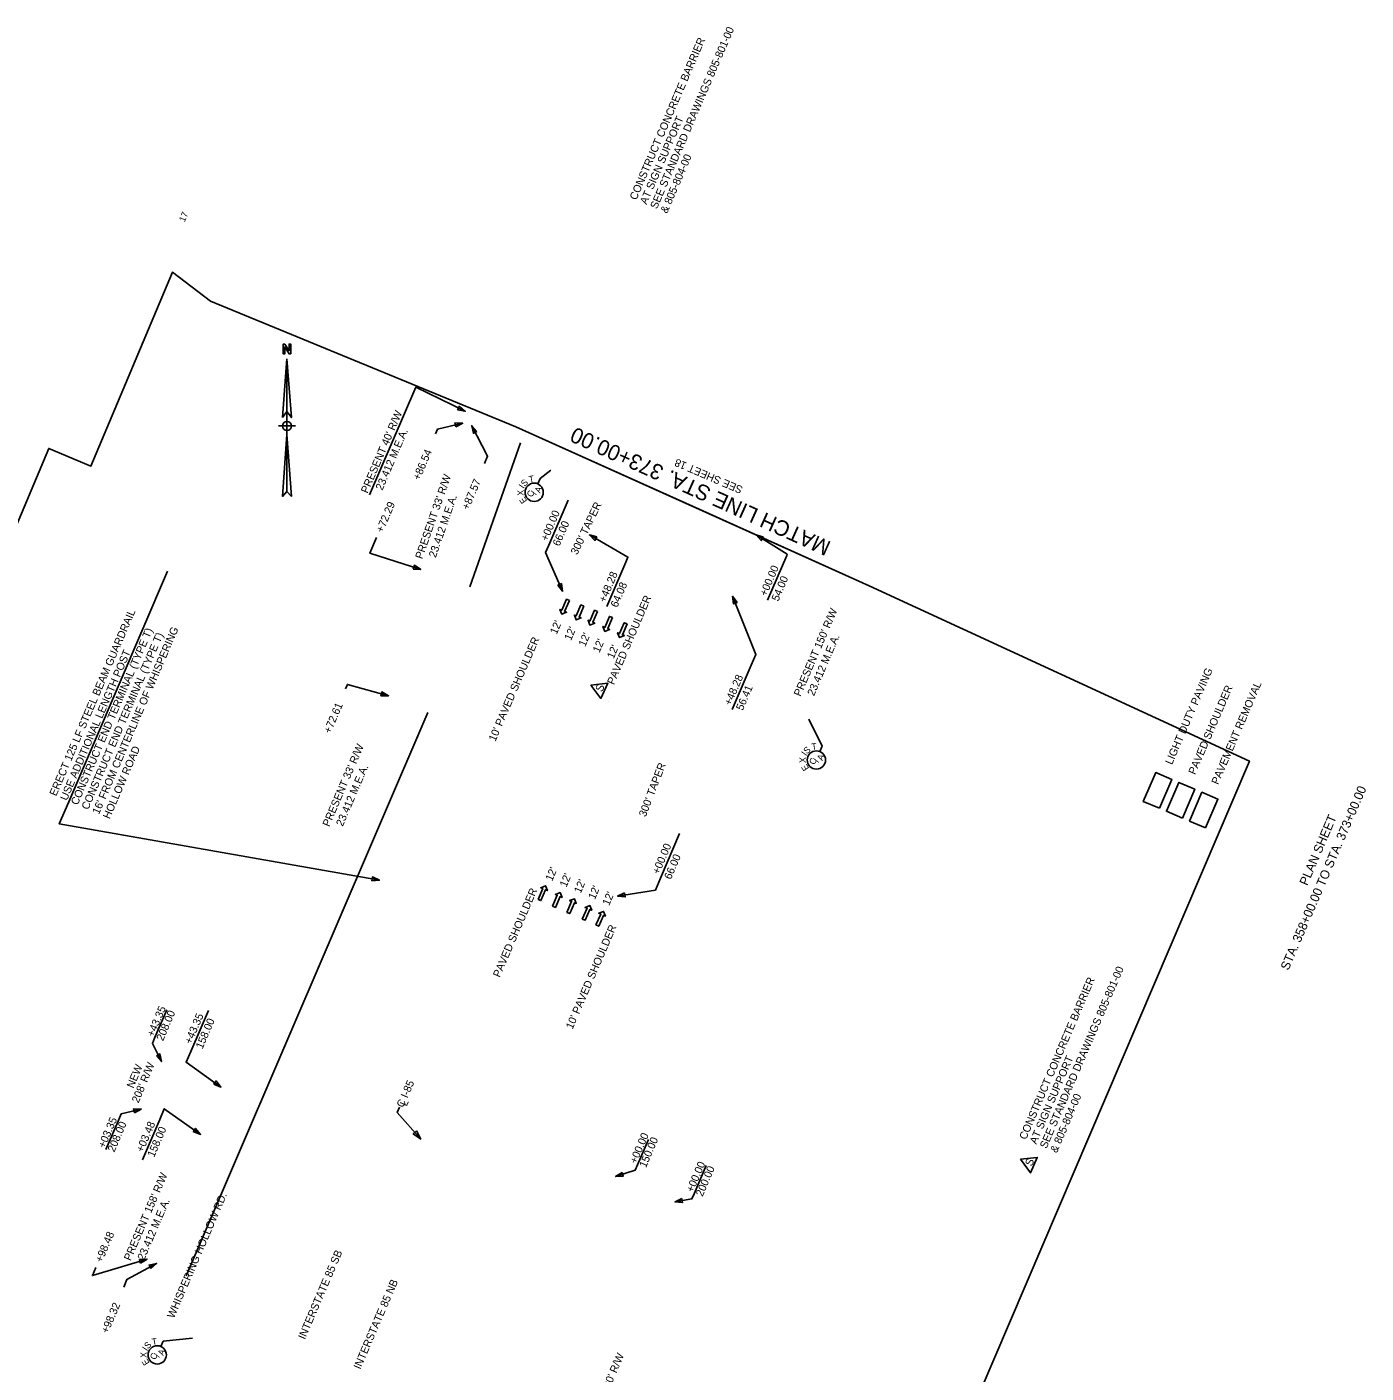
# Model space of a CAD drawing. Extents: x 1615013 to 1616950, y 1098171 to 1100198.
# Drawn here: x 1615717 to 1616753, y 1099157 to 1100198 of the extents above; entities that cross this region are included whole.
import ezdxf

# ---------------------------------------------------------------- set-up
doc = ezdxf.new("R2010")
doc.units = 0
for name, color, linetype in [('RD_DTM_BkLn1', 7, 'Continuous'), ('RD_DTM_Obscure', 7, 'Continuous'), ('RD_EX_BldgApp', 7, 'Continuous'), ('RD_EX_BldgChurch', 7, 'Continuous'), ('RD_EX_Driveway', 7, 'Continuous'), ('RD_EX_Fence_ChLk', 7, 'Continuous'), ('RD_EX_Misc', 7, 'Continuous'), ('RD_EX_Misc_Golf_Teebox', 7, 'Continuous'), ('RD_EX_RailRoad', 7, 'Continuous'), ('RD_EX_UT', 7, 'Continuous'), ('RD_EX_VEG', 7, 'Continuous'), ('RD_HC_Data', 7, 'Continuous')]:
    doc.layers.add(name, color=color, linetype=linetype)

msp = doc.modelspace()

# ---------------------------------------------------------------- linework, layer by layer
at = {"layer": 'RD_DTM_BkLn1'}
msp.add_lwpolyline([(1616021.6, 1099337.8), (1616003.5, 1099358.5), (1616005.2, 1099362.5)], dxfattribs=at)
msp.add_lwpolyline([(1616018.3, 1099344.1), (1616015.8, 1099341.8), (1616021.6, 1099337.8)], close=True, dxfattribs=at)
at = {"layer": 'RD_DTM_Obscure'}
for p, q in [((1616114, 1099848.9), (1616122.4, 1099855.4)), ((1616112.2, 1099844.7), (1616114, 1099848.9)), ((1616332.4, 1099641.9), (1616321.9, 1099662.6)), ((1616330.6, 1099637.7), (1616332.4, 1099641.9)), ((1615820.5, 1099177.4), (1615822.3, 1099181.6)), ((1615822.3, 1099181.6), (1615845.1, 1099183.8))]:
    msp.add_line(p, q, dxfattribs=at)
for centre in [(1616109.4, 1099838.2), (1616327.8, 1099631.1), (1615817.7, 1099170.9)]:
    msp.add_circle(centre, 7.08, dxfattribs=at)
at = {"layer": 'RD_EX_BldgApp'}
for points in [[(1615982.1, 1099836.2), (1616017.9, 1099919.6), (1616056.1, 1099900.9)], [(1616033, 1099883.3), (1616034.7, 1099887.1), (1616054.1, 1099891.6)], [(1616070.9, 1099860.5), (1616073.3, 1099866.1), (1616061.1, 1099889.7)], [(1615987.5, 1099803.1), (1615982.3, 1099791), (1616021.7, 1099778.5)], [(1615963.4, 1099686.2), (1615964.9, 1099689.5), (1615996.7, 1099680.8)], [(1615770.2, 1099238.5), (1615767.6, 1099232.3), (1615809.9, 1099245)], [(1615791.8, 1099223.4), (1615794.3, 1099229.3), (1615817.2, 1099241.7)]]:
    msp.add_lwpolyline(points, dxfattribs=at)
for points in [[(1616050.2, 1099902), (1616056.1, 1099900.9), (1616051.6, 1099904.8)], [(1616048.8, 1099888.8), (1616054.1, 1099891.6), (1616048.1, 1099891.8)], [(1616065.1, 1099885.3), (1616061.1, 1099889.7), (1616062.4, 1099883.9)], [(1616015.8, 1099778.7), (1616021.7, 1099778.5), (1616016.7, 1099781.7)], [(1615990.7, 1099680.8), (1615996.7, 1099680.8), (1615991.5, 1099683.8)], [(1615804.8, 1099241.8), (1615809.9, 1099245), (1615803.9, 1099244.8)], [(1615812.8, 1099237.6), (1615817.2, 1099241.7), (1615811.4, 1099240.3)]]:
    msp.add_lwpolyline(points, close=True, dxfattribs=at)
at = {"layer": 'RD_EX_Driveway'}
msp.add_line((1615825.7, 1099777.1), (1615749.2, 1099598.6), dxfattribs=at)
msp.add_lwpolyline([(1615749.2, 1099598.6), (1615741.9, 1099581.7), (1615989.6, 1099538)], dxfattribs=at)
msp.add_lwpolyline([(1615983.7, 1099537.5), (1615989.6, 1099538), (1615984.2, 1099540.6)], close=True, dxfattribs=at)
at = {"layer": 'RD_EX_Fence_ChLk'}
for p, q in [((1615825.1, 1099437.8), (1615815.7, 1099416)), ((1615857.3, 1099437.3), (1615843.6, 1099405.5)), ((1615787.4, 1099351.8), (1615778, 1099329.9)), ((1615819.6, 1099353), (1615806.2, 1099321.8)), ((1616197.9, 1099337.6), (1616189.4, 1099317.8)), ((1616242.6, 1099317.5), (1616233.2, 1099295.6))]:
    msp.add_line(p, q, dxfattribs=at)
for points in [[(1615815.7, 1099416), (1615814, 1099411.9), (1615821, 1099397.8)], [(1615843.6, 1099405.5), (1615840.1, 1099397.3), (1615867, 1099378.1)], [(1615787.4, 1099351.8), (1615789.7, 1099357.3), (1615805.3, 1099361.1)], [(1615819.6, 1099353), (1615823.2, 1099361.3), (1615851.3, 1099341.5)], [(1616189.4, 1099317.8), (1616187.6, 1099313.8), (1616172.4, 1099308.9)], [(1616233.2, 1099295.6), (1616231.5, 1099291.6), (1616218.4, 1099289.2)]]:
    msp.add_lwpolyline(points, dxfattribs=at)
for points in [[(1615817.1, 1099402.3), (1615821, 1099397.8), (1615819.8, 1099403.7)], [(1615861.4, 1099380.2), (1615867, 1099378.1), (1615863.2, 1099382.8)], [(1615800, 1099358.2), (1615805.3, 1099361.1), (1615799.3, 1099361.2)], [(1615845.6, 1099343.6), (1615851.3, 1099341.5), (1615847.4, 1099346.1)], [(1616177.4, 1099312.1), (1616172.4, 1099308.9), (1616178.4, 1099309.2)], [(1616223.8, 1099291.8), (1616218.4, 1099289.2), (1616224.3, 1099288.7)]]:
    msp.add_lwpolyline(points, close=True, dxfattribs=at)
at = {"layer": 'RD_EX_Misc'}
for points in [[(1616136.7, 1099754.4), (1616134.5, 1099755.4), (1616130.8, 1099746.9), (1616129.3, 1099747.6), (1616130.8, 1099743.9), (1616134.5, 1099745.4), (1616133, 1099746)], [(1616147.8, 1099750), (1616145.6, 1099751), (1616142, 1099742.6), (1616140.5, 1099743.2), (1616142, 1099739.5), (1616145.7, 1099741), (1616144.2, 1099741.6)], [(1616158.5, 1099746), (1616156.2, 1099746.9), (1616152.6, 1099738.5), (1616151.1, 1099739.2), (1616152.6, 1099735.4), (1616156.3, 1099736.9), (1616154.8, 1099737.6)], [(1616158.5, 1099746), (1616156.2, 1099746.9), (1616152.6, 1099738.5), (1616151.1, 1099739.2), (1616152.6, 1099735.4), (1616156.3, 1099736.9), (1616154.8, 1099737.6)], [(1616170, 1099741.2), (1616167.7, 1099742.1), (1616164.1, 1099733.7), (1616162.6, 1099734.4), (1616164.1, 1099730.6), (1616167.8, 1099732.1), (1616166.3, 1099732.8)], [(1616170, 1099741.2), (1616167.7, 1099742.1), (1616164.1, 1099733.7), (1616162.6, 1099734.4), (1616164.1, 1099730.6), (1616167.8, 1099732.1), (1616166.3, 1099732.8)], [(1616181.3, 1099736.4), (1616179.1, 1099737.3), (1616175.5, 1099728.9), (1616174, 1099729.5), (1616175.5, 1099725.8), (1616179.2, 1099727.3), (1616177.7, 1099727.9)], [(1616181.3, 1099736.4), (1616179.1, 1099737.3), (1616175.5, 1099728.9), (1616174, 1099729.5), (1616175.5, 1099725.8), (1616179.2, 1099727.3), (1616177.7, 1099727.9)], [(1616112.4, 1099523.2), (1616114.6, 1099522.3), (1616118.2, 1099530.7), (1616119.7, 1099530.1), (1616118.2, 1099533.8), (1616114.5, 1099532.3), (1616116, 1099531.6)], [(1616123.7, 1099517.9), (1616125.9, 1099517), (1616129.5, 1099525.4), (1616131, 1099524.8), (1616129.5, 1099528.5), (1616125.8, 1099527), (1616127.3, 1099526.4)], [(1616134.7, 1099513.2), (1616136.9, 1099512.3), (1616140.5, 1099520.7), (1616142, 1099520.1), (1616140.5, 1099523.8), (1616136.8, 1099522.3), (1616138.3, 1099521.7)], [(1616146.6, 1099508), (1616148.8, 1099507.1), (1616152.5, 1099515.5), (1616154, 1099514.8), (1616152.5, 1099518.5), (1616148.8, 1099517.1), (1616150.3, 1099516.4)], [(1616157.2, 1099503.5), (1616159.4, 1099502.5), (1616163.1, 1099510.9), (1616164.6, 1099510.3), (1616163.1, 1099514), (1616159.4, 1099512.5), (1616160.9, 1099511.9)]]:
    msp.add_lwpolyline(points, close=True, dxfattribs=at)
at = {"layer": 'RD_EX_Misc_Golf_Teebox'}
for p, q in [((1616135.6, 1099832), (1616120.8, 1099797.3)), ((1616180.3, 1099784.1), (1616165.6, 1099749.9)), ((1616305, 1099789.4), (1616290.1, 1099754.7)), ((1616277.4, 1099704.4), (1616262.7, 1099670.2)), ((1616167.1, 1099676.5), (1616167.1, 1099676.5)), ((1616221.9, 1099574.2), (1616207.1, 1099539.6))]:
    msp.add_line(p, q, dxfattribs=at)
for points in [[(1616180.3, 1099784.1), (1616182, 1099788.1), (1616152.2, 1099805.2)], [(1616305, 1099789.4), (1616305.3, 1099790.2), (1616281.1, 1099805.2)], [(1616120.8, 1099797.3), (1616118.3, 1099791.5), (1616131.4, 1099761.6)], [(1616277.4, 1099704.4), (1616281, 1099712.8), (1616263, 1099757.8)], [(1616593.2, 1099593.8), (1616602.8, 1099616.1), (1616590.4, 1099621.4), (1616580.8, 1099599.1), (1616593.2, 1099593.8)], [(1616611.1, 1099586.1), (1616620.6, 1099608.4), (1616608.3, 1099613.7), (1616598.7, 1099591.4), (1616611.1, 1099586.1)], [(1616628.9, 1099578.5), (1616638.5, 1099600.8), (1616626.1, 1099606.1), (1616616.6, 1099583.8), (1616628.9, 1099578.5)], [(1616207.1, 1099539.6), (1616203.2, 1099530.4), (1616174, 1099525.8)]]:
    msp.add_lwpolyline(points, dxfattribs=at)
for points in [[(1616158, 1099803.7), (1616152.2, 1099805.2), (1616156.4, 1099801)], [(1616286.9, 1099803.5), (1616281.1, 1099805.2), (1616285.2, 1099800.8)], [(1616127.7, 1099766.3), (1616131.4, 1099761.6), (1616130.5, 1099767.6)], [(1616266.6, 1099753), (1616263, 1099757.8), (1616263.7, 1099751.8)], [(1616153.3, 1099689.1), (1616161.1, 1099678.7), (1616166.3, 1099690.6)], [(1616593.2, 1099593.8), (1616602.8, 1099616.1), (1616590.4, 1099621.4), (1616580.8, 1099599.1)], [(1616611.1, 1099586.1), (1616620.6, 1099608.4), (1616608.3, 1099613.7), (1616598.7, 1099591.4)], [(1616628.9, 1099578.5), (1616638.5, 1099600.8), (1616626.1, 1099606.1), (1616616.6, 1099583.8)], [(1616179.4, 1099528.2), (1616174, 1099525.8), (1616179.9, 1099525.2)], [(1616485.8, 1099322.2), (1616493.6, 1099311.7), (1616498.7, 1099323.7)]]:
    msp.add_lwpolyline(points, close=True, dxfattribs=at)
at = {"layer": 'RD_EX_RailRoad'}
for p, q in [((1615918.1, 1099941.4), (1615914.7, 1099896)), ((1615918.1, 1099900.7), (1615914.7, 1099896)), ((1615918.1, 1099900.7), (1615918.1, 1099882.9)), ((1615924.6, 1099889.5), (1615911.6, 1099889.5)), ((1615918.1, 1099882.9), (1615921.5, 1099835)), ((1615921.5, 1099835), (1615918.1, 1099838.8))]:
    msp.add_line(p, q, dxfattribs=at)
msp.add_lwpolyline([(1615921, 1099945.2), (1615919.8, 1099945.2), (1615916.4, 1099950.6), (1615916.4, 1099949.8), (1615916.4, 1099945.2), (1615915.2, 1099945.2), (1615915.2, 1099952.8), (1615916.4, 1099952.8), (1615919.8, 1099947.7), (1615919.8, 1099948.1), (1615919.8, 1099952.8), (1615921, 1099952.8), (1615921, 1099945.2)], dxfattribs=at)
for points in [[(1615918.1, 1099941.4), (1615921.5, 1099896), (1615918.1, 1099900.7)], [(1615918.1, 1099882.9), (1615918.1, 1099838.8), (1615914.7, 1099835)]]:
    msp.add_lwpolyline(points, close=True, dxfattribs=at)
msp.add_circle((1615918.1, 1099889.5), 3.45, dxfattribs=at)
at = {"layer": 'RD_EX_UT'}
msp.add_lwpolyline([(1615502.7, 1098507.9), (1615778.5, 1098389.7), (1616070.1, 1098243.5), (1616662.9, 1099630.3), (1616368.7, 1099765.8), (1616095.1, 1099888.9), (1615859, 1099986), (1615829.5, 1100008.4), (1615766.4, 1099858.4), (1615733.7, 1099872.1), (1615213.1, 1098634.6)], close=True, dxfattribs=at)
msp.add_lwpolyline([(1615502.7, 1098507.9), (1615778.5, 1098389.7), (1616070.1, 1098243.5), (1616662.9, 1099630.3), (1616368.7, 1099765.8), (1616095.1, 1099888.9), (1615859, 1099986), (1615829.5, 1100008.4), (1615766.4, 1099858.4), (1615733.7, 1099872.1), (1615213.1, 1098634.6)], close=True, dxfattribs=at)
at = {"layer": 'RD_EX_VEG'}
msp.add_lwpolyline([(1616368.7, 1099765.8), (1616231.9, 1099827.4), (1616095.1, 1099888.9)], dxfattribs=at)
at = {"layer": 'RD_HC_Data'}
for p, q in [((1616098.8, 1099876.4), (1616059.5, 1099765.1)), ((1615840.2, 1099232), (1616027, 1099667.8))]:
    msp.add_line(p, q, dxfattribs=at)

# ---------------------------------------------------------------- texts
at = {"layer": 'RD_DTM_BkLn1'}
for s, height, rotation, p in [('STA. 358+00.00 TO STA. 373+00.00', 6.983, 66.7846, (1616693.1, 1099467.9)), ('PLAN SHEET', 6.98, 66.7846, (1616707.7, 1099533.4)), ('C I-85', 6, 66.3699, (1616008.1, 1099361.7)), ('L', 6, 66.3699, (1616010.7, 1099362.8)), ('WHISPERING HOLLOW RD.', 6, 66.7846, (1615830.6, 1099198.7)), ('INTERSTATE 85 SB', 6, 66.8087, (1615932, 1099182.4)), ('INTERSTATE 85 NB', 6, 66.8087, (1615974.9, 1099159.3))]:
    msp.add_text(s, height=height, rotation=rotation, dxfattribs=at).set_placement(p)
at = {"layer": 'RD_DTM_Obscure'}
for s, rotation, p in [('I', 56.7167, (1616101.3, 1099840.6)), ('S', 44.9962, (1616102, 1099842.2)), ('T', 9.8347, (1616105.7, 1099845.7)), ('X', 91.8781, (1616101.4, 1099835.6)), ('E', 125.3653, (1616104.2, 1099831.6)), ('C', 66.7814, (1616108, 1099834)), ('/', 66.7814, (1616111.1, 1099835.9)), ('A', 66.7814, (1616114, 1099837.2)), ('I', 54.7645, (1616319.8, 1099633.9)), ('S', 43.044, (1616320.6, 1099635.4)), ('T', 7.8826, (1616324.4, 1099638.8)), ('X', 89.926, (1616319.7, 1099628.8)), ('E', 123.4131, (1616322.4, 1099624.7)), ('C', 66.7814, (1616326.5, 1099627)), ('/', 66.7814, (1616329.6, 1099628.9)), ('A', 66.7814, (1616332.5, 1099630.2)), ('I', 55.8808, (1615809.8, 1099173.5)), ('S', 44.1603, (1615810.5, 1099175.1)), ('T', 10.6731, (1615814, 1099178.4)), ('X', 89.926, (1615809.6, 1099168.6)), ('E', 121.7388, (1615812, 1099164.7)), ('C', 66.7814, (1615816.4, 1099166.7)), ('/', 66.7814, (1615819.5, 1099168.6)), ('A', 66.7814, (1615822.4, 1099169.9))]:
    msp.add_text(s, height=5, rotation=rotation, dxfattribs=at).set_placement(p)
at = {"layer": 'RD_EX_BldgApp'}
for s, rotation, p in [("PRESENT 40' R/W", 66.7846, (1615980.5, 1099836.9)), ('23.412 M.E.A.', 66.7846, (1615991.9, 1099839.2)), ('+86.54', 66.7846, (1616020.7, 1099847)), ("PRESENT 33' R/W", 70.9127, (1616022.8, 1099786.1)), ('+87.57', 66.7846, (1616058.6, 1099824.1)), ('  23.412 M.E.A.', 70.9127, (1616031.8, 1099783)), ('+72.29', 66.7846, (1615992.2, 1099806.5)), ("PRESENT 150' R/W ", 66.7846, (1616315.5, 1099679.8)), ('  23.412 M.E.A.', 66.7846, (1616324.2, 1099676.1)), ('+72.61', 66.7846, (1615951.7, 1099651.1)), ("PRESENT 33' R/W ", 66.7846, (1615950.8, 1099579)), ('  23.412 M.E.A.', 66.7846, (1615959.5, 1099575.2)), ("PRESENT 158' R/W ", 66.7846, (1615797.1, 1099243.2)), ('  23.412 M.E.A.', 66.7846, (1615805.8, 1099239.5)), ('+98.48', 66.7846, (1615774.9, 1099241.9)), ('+98.32', 66.7846, (1615779.5, 1099187))]:
    msp.add_text(s, height=6, rotation=rotation, dxfattribs=at).set_placement(p)
at = {"layer": 'RD_EX_BldgChurch'}
for s, rotation, p in [('NEW', 67.3945, (1615799.3, 1099376.7)), ("208' R/W", 67.3945, (1615803.2, 1099365.3)), ("NEW 200' R/W", 66.8024, (1616158, 1099121.3))]:
    msp.add_text(s, height=6, rotation=rotation, dxfattribs=at).set_placement(p)
at = {"layer": 'RD_EX_Driveway'}
for s, p in [('ERECT 125 LF STEEL BEAM GUARDRAIL', (1615739.5, 1099602.7)), ('CONSTRUCT END TERMINAL (TYPE T)', (1615756.1, 1099595.7)), ('CONSTRUCT END TERMINAL (TYPE T)', (1615764.3, 1099592.1)), ("16' FROM CENTERLINE OF WHISPERING", (1615772.6, 1099588.6)), ('USE ADDITIONAL LENGTH POST', (1615747.8, 1099599.2)), ('HOLLOW ROAD', (1615780.9, 1099585))]:
    msp.add_text(s, height=6, rotation=66.7863, dxfattribs=at).set_placement(p)
at = {"layer": 'RD_EX_Fence_ChLk'}
for s, rotation, p in [('+43.35', 66.8024, (1615814.9, 1099416.4)), ('208.00', 66.8024, (1615822.2, 1099413.3)), ('+43.35', 66.7846, (1615844, 1099410.8)), ('158.00', 66.7846, (1615852.7, 1099407.1)), ('+03.35', 66.8024, (1615777.1, 1099330.4)), ('208.00', 66.8024, (1615784.5, 1099327.3)), ('+03.48', 66.7846, (1615806.6, 1099327.1)), ('158.00', 66.7846, (1615815.3, 1099323.3)), ('+00.00', 66.8024, (1616188.5, 1099318.3)), ('150.00', 66.8024, (1616195.9, 1099315.2)), ('+00.00', 66.8024, (1616232.3, 1099296.1)), ('200.00', 66.8024, (1616239.7, 1099292.9))]:
    msp.add_text(s, height=6, rotation=rotation, dxfattribs=at).set_placement(p)
at = {"layer": 'RD_EX_Misc_Golf_Teebox'}
for s, height, rotation, p in [('SEE STANDARD DRAWINGS 805-801-00', 6, 66.7846, (1616204.4, 1100056.9)), ('CONSTRUCT CONCRETE BARRIER ', 6, 66.7846, (1616188.5, 1100063.8)), ('AT SIGN SUPPORT', 6, 66.7846, (1616196.4, 1100060.4)), ('& 805-804-00', 6, 66.7846, (1616212.3, 1100053.5)), ('17', 5, 66.7846, (1615838.9, 1100046.9)), ('+00.00', 6, 66.7846, (1616119.7, 1099799.9)), ("300' TAPER", 6, 64.3033, (1616142.7, 1099789.3)), ('66.00', 6, 66.7846, (1616128.9, 1099796)), ('+00.00', 6, 66.7846, (1616289.1, 1099757.3)), ('+48.28', 6, 66.7846, (1616164.5, 1099752.5)), ('54.00', 6, 66.7846, (1616298.3, 1099753.4)), ('64.08', 6, 66.7846, (1616173.7, 1099748.6)), (' PAVED SHOULDER', 6, 66.783, (1616170.2, 1099686.8)), ("12'", 6, 66.7814, (1616126.8, 1099727.8)), ("12'", 6, 66.7814, (1616137.9, 1099723)), ("12'", 6, 66.7814, (1616148.9, 1099718.3)), ("10' PAVED SHOULDER", 6, 66.783, (1616079.4, 1099645)), ("12'", 6, 66.7814, (1616159.9, 1099713.6)), ("12'", 6, 66.7814, (1616170.9, 1099708.9)), ('LIGHT DUTY PAVING', 6, 66.7846, (1616603, 1099627)), ('S', 6, 66.7846, (1616162, 1099683.3)), ('+48.28', 6, 66.7846, (1616261.6, 1099672.8)), ('56.41', 6, 66.7846, (1616270.8, 1099668.9)), ('PAVED SHOULDER', 6, 66.7846, (1616620.9, 1099619.3)), ('PAVEMENT REMOVAL', 6, 66.7846, (1616638.7, 1099611.6)), ("300' TAPER", 6, 69.0133, (1616195.7, 1099586.6)), ('+00.00', 6, 66.7846, (1616206, 1099542.2)), ('66.00', 6, 66.7846, (1616215.2, 1099538.2)), ("12'", 6, 66.7814, (1616123.3, 1099536.9)), ("12'", 6, 66.7814, (1616134.3, 1099532.2)), (' PAVED SHOULDER', 6, 66.783, (1616081.9, 1099460.4)), ("12'", 6, 66.7814, (1616145.4, 1099527.5)), ("12'", 6, 66.7814, (1616156.4, 1099522.7)), ("12'", 6, 66.7814, (1616167.4, 1099518)), ("10' PAVED SHOULDER", 6, 66.783, (1616139.1, 1099422.4)), ('SEE STANDARD DRAWINGS 805-801-00', 6, 66.7846, (1616505.9, 1099330.1)), ('CONSTRUCT CONCRETE BARRIER ', 6, 66.7846, (1616490, 1099336.9)), ('AT SIGN SUPPORT', 6, 66.7846, (1616498, 1099333.5)), ('& 805-804-00', 6, 66.7846, (1616513.9, 1099326.7)), ('S', 6, 66.7846, (1616494.5, 1099316.4))]:
    msp.add_text(s, height=height, rotation=rotation, dxfattribs=at).set_placement(p)
at = {"layer": 'RD_EX_VEG'}
for s, height, rotation, p in [('MATCH LINE STA. 373+00.00', 12, 155.7736, (1616339.9, 1099799.6)), ('SEE SHEET 18', 6, 156.8359, (1616271.4, 1099842.3))]:
    msp.add_text(s, height=height, rotation=rotation, dxfattribs=at).set_placement(p)

doc.saveas('drawing.dxf')
